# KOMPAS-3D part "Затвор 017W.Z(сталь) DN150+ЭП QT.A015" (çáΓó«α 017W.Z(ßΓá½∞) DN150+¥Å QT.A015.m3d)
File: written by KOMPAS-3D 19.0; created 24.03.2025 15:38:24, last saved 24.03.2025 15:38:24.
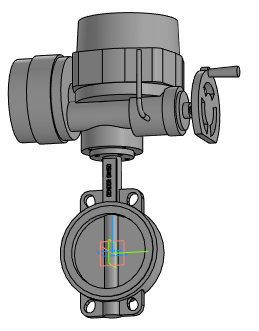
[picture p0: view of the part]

Document properties: Полное имя файла: Затвор 017W.Z(сталь) DN150+ЭП QT.A015.a3d

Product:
- Part/product: Затвор 017W.Z(сталь) DN150+ЭП QT.A015
    Масса: 99.1937

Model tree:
1. Операция без истории:1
